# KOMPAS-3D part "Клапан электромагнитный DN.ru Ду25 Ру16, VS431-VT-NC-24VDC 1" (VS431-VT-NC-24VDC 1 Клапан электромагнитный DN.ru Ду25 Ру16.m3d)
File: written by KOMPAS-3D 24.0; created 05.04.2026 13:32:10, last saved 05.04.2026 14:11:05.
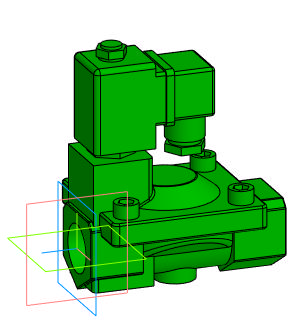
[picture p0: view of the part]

Document properties: Автор: artio; Полное имя файла: C:\Users\artio\OneDrive\Рабочий стол\Клапан электромагнитный DN.ru\VS431\VS431-VT-NC\VS431-VT-NC-24VDC\Ду25\VS431-VT-NC-24VDC 1 Клапан электромагнитный DN.ru Ду25 Ру16.m3d

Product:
- Body: Тело 1  | qty 1
    Масса: 1.729172
- Part/product: Клапан электромагнитный DN.ru Ду25 Ру16  | designation VS431-VT-NC-24VDC 1
    Масса: 1.267
    Раздел спецификации: Прочие изделия
    Примечание: D130-04756
    additional columns: ef56311e-7521-43dc-8291-0e6108b3d81d; artio; c; Шероховатость не задана; Да

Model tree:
1. Операция без истории:1

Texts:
  VS431-VT-NC-24VDC 1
